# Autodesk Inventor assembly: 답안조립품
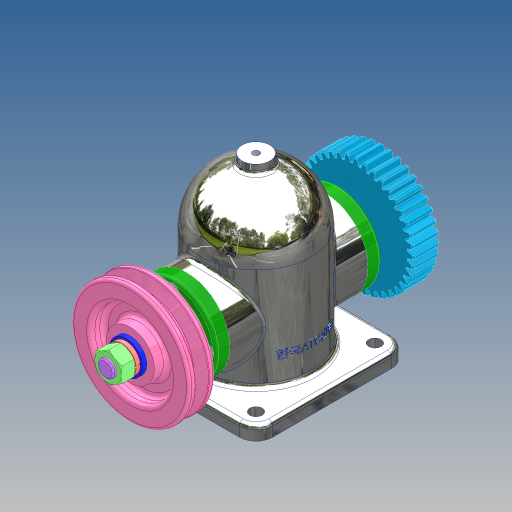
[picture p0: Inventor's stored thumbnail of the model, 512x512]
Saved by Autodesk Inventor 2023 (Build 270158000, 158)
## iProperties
Created: 2025-04
Part Number: 답안조립품
Document SubType Name: Assembly
Designer: Admin
Author: Admin
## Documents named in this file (14)
- C:\Users\Admin\Desktop\750406V1017\답안조립품.iam
- C:\Users\Admin\Desktop\750406V1017\본체.ipt
- C:\Users\Admin\Desktop\750406V1017\가져온 구성요소\스프링 와셔 M12\스프링 와셔 M12.ipt
- C:\Users\Admin\Desktop\750406V1017\가져온 구성요소\오일 실 26 38 8\오일 실 26 38 8.ipt
- C:\Users\Admin\Desktop\750406V1017\가져온 구성요소\축\축.ipt
- C:\Users\Admin\Desktop\750406V1017\가져온 구성요소\칼라\칼라.ipt
- C:\Users\Admin\Desktop\750406V1017\가져온 구성요소\커버\커버.ipt
- C:\Users\Admin\Desktop\750406V1017\가져온 구성요소\평와셔 M12\평와셔 M12.ipt
- C:\Users\Admin\Desktop\750406V1017\가져온 구성요소\평행 키 5x5x12\평행 키 5x5x12.ipt
- C:\Users\Admin\Desktop\750406V1017\가져온 구성요소\6각 구멍붙이 볼트 M4x12\6각 구멍붙이 볼트 M4x12.ipt
- C:\Users\Admin\Desktop\750406V1017\가져온 구성요소\6각 너트 M12x1\6각 너트 M12x1.ipt
- C:\Users\Admin\Desktop\750406V1017\가져온 구성요소\V 벨트 풀리\V 벨트 풀리.ipt
- C:\Users\Admin\Desktop\750406V1017\가져온 구성요소\깊은 홈 볼 베어링 6203\깊은 홈 볼 베어링 6203.ipt
- C:\Users\Admin\Desktop\750406V1017\스퍼기어.ipt
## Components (11 placed, 3 different names)
1. 6각 너트 M12x1:1
2. V 벨트 풀리:1
3. 6각 너트 M12x1:2
4. 6각 구멍붙이 볼트 M4x12:2
5. 6각 구멍붙이 볼트 M4x12:3
6. 6각 구멍붙이 볼트 M4x12:4
7. 6각 구멍붙이 볼트 M4x12:5
8. 6각 구멍붙이 볼트 M4x12:1
9. 6각 구멍붙이 볼트 M4x12:6
10. 6각 구멍붙이 볼트 M4x12:7
11. 6각 구멍붙이 볼트 M4x12:8
